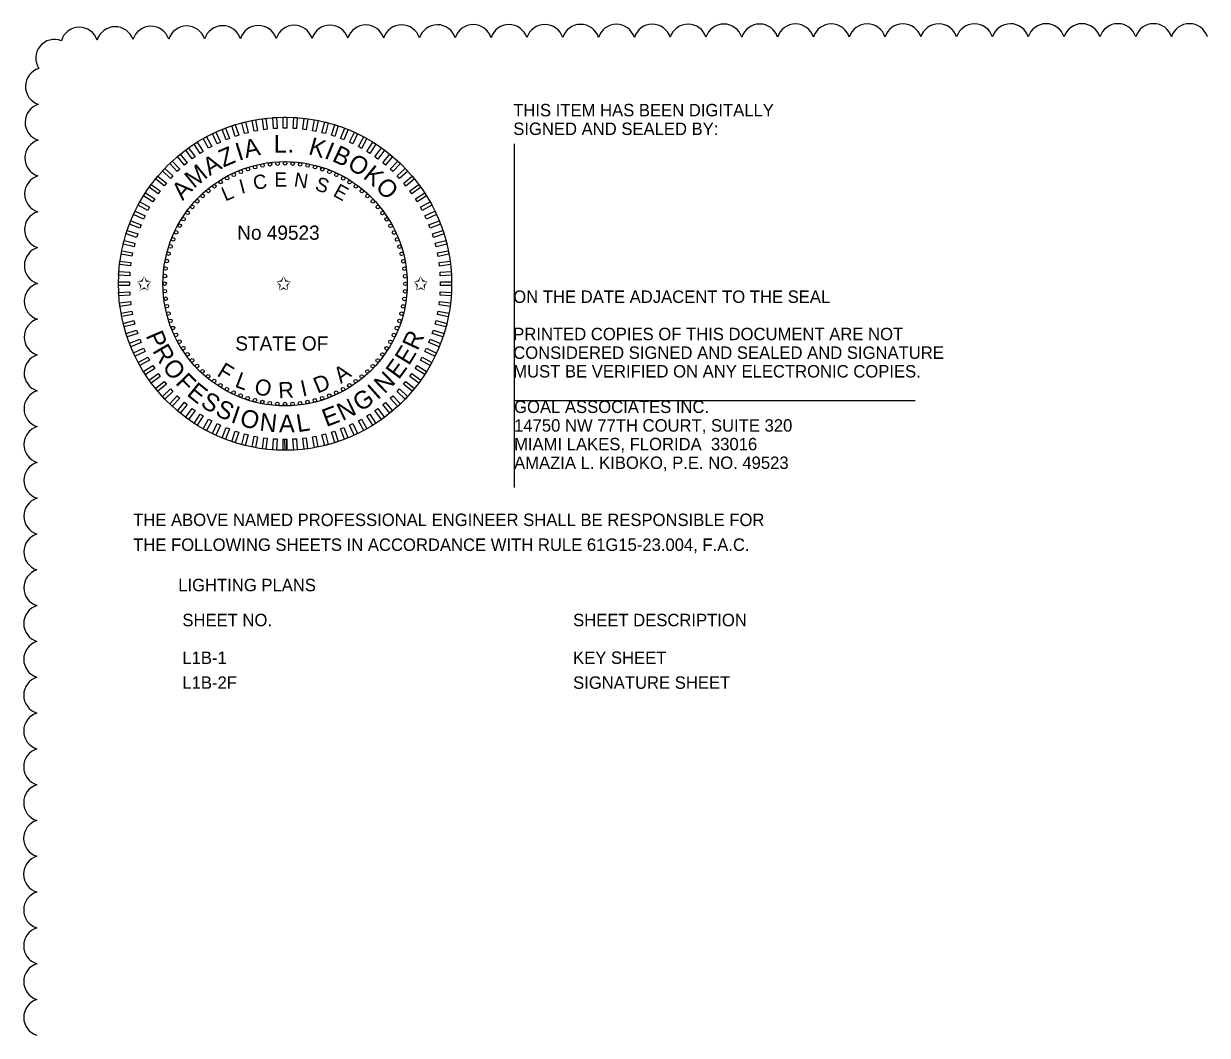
# Model space of a CAD drawing. Extents: x -811.2 to -767.6, y -2295.2 to -2235.1.
# Drawn here: x -783.68 to -777.02, y -2265.59 to -2259.9 of the extents above; entities that cross this region are included whole.
import ezdxf

# ---------------------------------------------------------------- set-up
doc = ezdxf.new("R2010")
doc.units = 0
for name, color, linetype in [('AdhocPoint_dp', 7, 'Continuous'), ('Cloud_dp', 7, 'Continuous'), ('PlotBorder_dp', 7, 'Continuous'), ('TextMinor', 7, 'Continuous'), ('TextMisc', 7, 'Continuous'), ('TextShtNo', 7, 'Continuous')]:
    doc.layers.add(name, color=color, linetype=linetype)

msp = doc.modelspace()

# ---------------------------------------------------------------- linework, layer by layer
at = {"layer": 'AdhocPoint_dp'}
for p, q in [((-780.9186, -2260.5734), (-780.9186, -2262.5081)), ((-780.9186, -2262.0181), (-778.6618, -2262.0181))]:
    msp.add_line(p, q, dxfattribs=at)
at = {"layer": 'Cloud_dp'}
for centre, start, end in [((-782.5594, -2260.0139), 17.87787, 162.87787), ((-782.3579, -2260.0127), 17.82689, 162.82689), ((-782.1564, -2260.0116), 17.78716, 162.78716), ((-781.9548, -2260.0107), 17.75505, 162.75505), ((-781.7533, -2260.0098), 17.72841, 162.72841), ((-781.5518, -2260.009), 17.70584, 162.70584), ((-781.3502, -2260.0084), 17.6864, 162.6864), ((-781.1487, -2260.0077), 17.66942, 162.66942), ((-780.9472, -2260.0072), 17.65443, 162.65443), ((-780.7456, -2260.0066), 17.64106, 162.64106), ((-780.5441, -2260.0062), 17.62905, 162.62905), ((-780.3425, -2260.0057), 17.61817, 162.61817), ((-780.141, -2260.0053), 17.60826, 162.60826), ((-779.9394, -2260.005), 17.59919, 162.59919), ((-779.7379, -2260.0046), 17.59084, 162.59084), ((-779.5364, -2260.0043), 17.58312, 162.58312), ((-779.3348, -2260.004), 17.57595, 162.57595), ((-779.1333, -2260.0038), 17.56928, 162.56928), ((-778.9317, -2260.0036), 17.56305, 162.56305), ((-778.7302, -2260.0033), 17.55721, 162.55721), ((-778.5286, -2260.0032), 17.55172, 162.55172), ((-778.3271, -2260.003), 17.54655, 162.54655), ((-778.1255, -2260.0028), 17.54167, 162.54167), ((-777.924, -2260.0027), 17.53705, 162.53705), ((-777.7224, -2260.0026), 17.53267, 162.53267), ((-777.5209, -2260.0025), 17.52851, 162.52851), ((-777.3194, -2260.0024), 17.52455, 162.52455), ((-777.1178, -2260.0023), 17.52079, 162.52079), ((-783.3652, -2260.0225), 18.59454, 163.59454), ((-783.1638, -2260.0193), 18.21421, 163.21421), ((-782.9624, -2260.0171), 18.04696, 163.04696), ((-782.7609, -2260.0154), 17.94666, 162.94666), ((-783.5053, -2260.0909), 68.43954, 213.43954), ((-783.563, -2260.2503), 106.80445, 251.80445), ((-783.565, -2260.4517), 107.04367, 252.04367), ((-783.5664, -2260.6532), 107.15618, 252.15618), ((-783.5675, -2260.8547), 107.22533, 252.22533), ((-783.5684, -2261.0562), 107.27338, 252.27338), ((-783.5691, -2261.2578), 107.30928, 252.30928), ((-783.5697, -2261.4593), 107.33743, 252.33743), ((-783.5703, -2261.6608), 107.36027, 252.36027), ((-783.5707, -2261.8624), 107.37928, 252.37928), ((-783.5711, -2262.0639), 107.39543, 252.39543), ((-783.5715, -2262.2655), 107.40937, 252.40937), ((-783.5717, -2262.467), 107.42156, 252.42156), ((-783.572, -2262.6685), 107.43234, 252.43234), ((-783.5722, -2262.8701), 107.44197, 252.44197), ((-783.5724, -2263.0716), 107.45063, 252.45063), ((-783.5726, -2263.2732), 107.45847, 252.45847), ((-783.5727, -2263.4747), 107.46563, 252.46563), ((-783.5728, -2263.6763), 107.47218, 252.47218), ((-783.5729, -2263.8778), 107.47822, 252.47822), ((-783.573, -2264.0794), 107.4838, 252.4838), ((-783.573, -2264.2809), 107.48899, 252.48899), ((-783.5731, -2264.4824), 107.49382, 252.49382), ((-783.5731, -2264.684), 107.49843, 252.49843), ((-783.573, -2264.8855), 107.51148, 252.51148), ((-783.573, -2265.0871), 107.53101, 252.53101), ((-783.5728, -2265.2886), 107.55191, 252.55191), ((-783.5726, -2265.4901), 107.57435, 252.57435)]:
    msp.add_arc(centre, 0.1057, start, end, dxfattribs=at)
at = {"layer": 'TextMinor'}
for radius in [0.9375, 0.6875]:
    msp.add_circle((-782.2078, -2261.3603), radius, dxfattribs=at)
at = {"layer": 'TextShtNo'}
for p, q in [((-782.2178, -2262.2978), (-782.218, -2262.2353)), ((-782.2078, -2262.2978), (-782.208, -2262.2353)), ((-782.1978, -2262.2978), (-782.198, -2262.2353))]:
    msp.add_line(p, q, dxfattribs=at)
for points in [[(-782.3618, -2260.4989), (-782.3816, -2260.5026), (-782.3933, -2260.4413), (-782.3735, -2260.4375)], [(-782.3074, -2260.4909), (-782.3274, -2260.4934), (-782.3352, -2260.4315), (-782.3152, -2260.4289)], [(-782.2526, -2260.4864), (-782.2727, -2260.4876), (-782.2767, -2260.4253), (-782.2565, -2260.424)], [(-782.1976, -2260.4853), (-782.2178, -2260.4853), (-782.2178, -2260.4228), (-782.1976, -2260.4228)], [(-782.1427, -2260.4876), (-782.1629, -2260.4864), (-782.1589, -2260.4241), (-782.1388, -2260.4253)], [(-782.088, -2260.4934), (-782.1081, -2260.4909), (-782.1002, -2260.429), (-782.0802, -2260.4315)], [(-782.0338, -2260.5027), (-782.0537, -2260.4989), (-782.042, -2260.4376), (-782.0221, -2260.4413)], [(-782.5712, -2260.5642), (-782.5894, -2260.5728), (-782.616, -2260.5163), (-782.5978, -2260.5077)], [(-782.5205, -2260.543), (-782.5392, -2260.5504), (-782.5622, -2260.4923), (-782.5434, -2260.4849)], [(-782.4685, -2260.525), (-782.4877, -2260.5312), (-782.507, -2260.4718), (-782.4878, -2260.4656)], [(-782.4156, -2260.5102), (-782.4351, -2260.5152), (-782.4506, -2260.4548), (-782.4311, -2260.4498)], [(-781.9803, -2260.5153), (-781.9999, -2260.5103), (-781.9844, -2260.4498), (-781.9648, -2260.4548)], [(-781.9277, -2260.5312), (-781.9469, -2260.525), (-781.9276, -2260.4656), (-781.9084, -2260.4719)], [(-781.8762, -2260.5505), (-781.895, -2260.543), (-781.872, -2260.485), (-781.8532, -2260.4924)], [(-781.826, -2260.5729), (-781.8443, -2260.5643), (-781.8177, -2260.5078), (-781.7994, -2260.5164)], [(-782.6681, -2260.616), (-782.6851, -2260.6268), (-782.7186, -2260.5741), (-782.7015, -2260.5633)], [(-782.6204, -2260.5886), (-782.6381, -2260.5983), (-782.6682, -2260.5436), (-782.6505, -2260.5339)], [(-781.7773, -2260.5984), (-781.795, -2260.5887), (-781.7649, -2260.534), (-781.7473, -2260.5437)], [(-781.7303, -2260.6269), (-781.7474, -2260.6161), (-781.7139, -2260.5634), (-781.6969, -2260.5742)], [(-782.7577, -2260.6796), (-782.7733, -2260.6925), (-782.8131, -2260.6443), (-782.7975, -2260.6315)], [(-782.7139, -2260.6464), (-782.7302, -2260.6583), (-782.7669, -2260.6078), (-782.7506, -2260.5959)], [(-781.6852, -2260.6584), (-781.7016, -2260.6465), (-781.6649, -2260.596), (-781.6485, -2260.6079)], [(-781.6422, -2260.6926), (-781.6578, -2260.6797), (-781.618, -2260.6316), (-781.6024, -2260.6445)], [(-782.7994, -2260.7155), (-782.8141, -2260.7293), (-782.8568, -2260.6838), (-782.8421, -2260.6699)], [(-781.6014, -2260.7294), (-781.6161, -2260.7156), (-781.5734, -2260.6701), (-781.5586, -2260.6839)], [(-782.8755, -2260.7947), (-782.8884, -2260.8102), (-782.9365, -2260.7704), (-782.9237, -2260.7549)], [(-782.8387, -2260.7539), (-782.8525, -2260.7686), (-782.898, -2260.7258), (-782.8842, -2260.7111)], [(-781.563, -2260.7687), (-781.5768, -2260.754), (-781.5313, -2260.7113), (-781.5175, -2260.726)], [(-781.5271, -2260.8104), (-781.54, -2260.7948), (-781.4919, -2260.755), (-781.479, -2260.7706)], [(-782.9097, -2260.8377), (-782.9216, -2260.8541), (-782.9721, -2260.8174), (-782.9603, -2260.801)], [(-781.4939, -2260.8542), (-781.5058, -2260.8379), (-781.4553, -2260.8012), (-781.4434, -2260.8175)], [(-782.9697, -2260.9298), (-782.9794, -2260.9475), (-783.0341, -2260.9174), (-783.0244, -2260.8997)], [(-782.9412, -2260.8828), (-782.952, -2260.8999), (-783.0047, -2260.8664), (-782.9939, -2260.8494)], [(-781.4635, -2260.9), (-781.4744, -2260.883), (-781.4216, -2260.8495), (-781.4108, -2260.8666)], [(-781.4361, -2260.9477), (-781.4458, -2260.93), (-781.3911, -2260.8999), (-781.3814, -2260.9176)], [(-782.9952, -2260.9785), (-783.0038, -2260.9968), (-783.0603, -2260.9702), (-783.0517, -2260.9519)], [(-781.4117, -2260.9969), (-781.4203, -2260.9787), (-781.3638, -2260.9521), (-781.3552, -2260.9704)], [(-783.0176, -2261.0287), (-783.0251, -2261.0475), (-783.0831, -2261.0245), (-783.0757, -2261.0057)], [(-781.3905, -2261.0477), (-781.3979, -2261.0289), (-781.3399, -2261.0059), (-781.3324, -2261.0247)], [(-783.0369, -2261.0802), (-783.0431, -2261.0994), (-783.1025, -2261.0801), (-783.0963, -2261.0609)], [(-781.3725, -2261.0996), (-781.3787, -2261.0804), (-781.3193, -2261.0611), (-781.3131, -2261.0803)], [(-783.0654, -2261.1863), (-783.0692, -2261.2062), (-783.1306, -2261.1945), (-783.1268, -2261.1746)], [(-783.0528, -2261.1328), (-783.0578, -2261.1524), (-783.1183, -2261.1368), (-783.1133, -2261.1173)], [(-781.3577, -2261.1526), (-781.3628, -2261.133), (-781.3023, -2261.1175), (-781.2973, -2261.137)], [(-781.3464, -2261.2063), (-781.3502, -2261.1865), (-781.2888, -2261.1748), (-781.285, -2261.1946)], [(-783.0747, -2261.2405), (-783.0772, -2261.2606), (-783.1391, -2261.2527), (-783.1366, -2261.2327)], [(-781.3384, -2261.2607), (-781.3409, -2261.2407), (-781.279, -2261.2329), (-781.2765, -2261.2529)], [(-783.0805, -2261.2952), (-783.0817, -2261.3153), (-783.1441, -2261.3114), (-783.1428, -2261.2913)], [(-781.3339, -2261.3155), (-781.3351, -2261.2954), (-781.2728, -2261.2915), (-781.2716, -2261.3116)], [(-783.0828, -2261.3501), (-783.0828, -2261.3703), (-783.1453, -2261.3703), (-783.1453, -2261.3501)], [(-781.3328, -2261.3705), (-781.3328, -2261.3503), (-781.2703, -2261.3503), (-781.2703, -2261.3705)], [(-783.0818, -2261.4051), (-783.0805, -2261.4252), (-783.1428, -2261.4291), (-783.1441, -2261.409)], [(-781.3351, -2261.4254), (-781.3339, -2261.4053), (-781.2716, -2261.4092), (-781.2728, -2261.4293)], [(-783.0772, -2261.4599), (-783.0747, -2261.4799), (-783.1366, -2261.4877), (-783.1392, -2261.4677)], [(-781.341, -2261.4801), (-781.3384, -2261.4601), (-781.2765, -2261.4679), (-781.279, -2261.4879)], [(-783.0693, -2261.5143), (-783.0655, -2261.5341), (-783.1268, -2261.5458), (-783.1306, -2261.526)], [(-783.0579, -2261.568), (-783.0529, -2261.5876), (-783.1133, -2261.6031), (-783.1184, -2261.5836)], [(-781.3628, -2261.5878), (-781.3578, -2261.5682), (-781.2973, -2261.5838), (-781.3023, -2261.6033)], [(-781.3502, -2261.5343), (-781.3464, -2261.5144), (-781.2851, -2261.5261), (-781.2889, -2261.546)], [(-783.0432, -2261.621), (-783.0369, -2261.6402), (-783.0963, -2261.6595), (-783.1025, -2261.6403)], [(-781.3788, -2261.6404), (-781.3725, -2261.6212), (-781.3131, -2261.6405), (-781.3194, -2261.6597)], [(-783.0251, -2261.673), (-783.0177, -2261.6917), (-783.0758, -2261.7147), (-783.0832, -2261.6959)], [(-781.398, -2261.6919), (-781.3906, -2261.6731), (-781.3325, -2261.6961), (-781.3399, -2261.7149)], [(-783.0039, -2261.7237), (-782.9953, -2261.7419), (-783.0518, -2261.7685), (-783.0604, -2261.7502)], [(-782.9795, -2261.7729), (-782.9698, -2261.7906), (-783.0245, -2261.8207), (-783.0342, -2261.803)], [(-781.4459, -2261.7908), (-781.4362, -2261.7731), (-781.3815, -2261.8032), (-781.3912, -2261.8209)], [(-781.4204, -2261.7421), (-781.4118, -2261.7238), (-781.3553, -2261.7504), (-781.3639, -2261.7687)], [(-782.9521, -2261.8206), (-782.9413, -2261.8376), (-782.994, -2261.8711), (-783.0048, -2261.854)], [(-781.4745, -2261.8378), (-781.4636, -2261.8207), (-781.4109, -2261.8542), (-781.4217, -2261.8712)], [(-782.9217, -2261.8664), (-782.9099, -2261.8827), (-782.9604, -2261.9194), (-782.9722, -2261.9031)], [(-781.5059, -2261.8829), (-781.494, -2261.8665), (-781.4435, -2261.9032), (-781.4554, -2261.9196)], [(-782.8885, -2261.9102), (-782.8757, -2261.9258), (-782.9238, -2261.9656), (-782.9366, -2261.95)], [(-782.8527, -2261.9519), (-782.8388, -2261.9666), (-782.8844, -2262.0093), (-782.8982, -2261.9946)], [(-781.5769, -2261.9667), (-781.5631, -2261.952), (-781.5176, -2261.9948), (-781.5314, -2262.0095)], [(-781.5401, -2261.9259), (-781.5272, -2261.9104), (-781.4791, -2261.9502), (-781.492, -2261.9657)], [(-782.8142, -2261.9912), (-782.7995, -2262.005), (-782.8423, -2262.0505), (-782.857, -2262.0367)], [(-782.7734, -2262.028), (-782.7579, -2262.0409), (-782.7977, -2262.089), (-782.8132, -2262.0761)], [(-781.6579, -2262.041), (-781.6423, -2262.0281), (-781.6025, -2262.0763), (-781.6181, -2262.0891)], [(-781.6162, -2262.0051), (-781.6015, -2261.9913), (-781.5588, -2262.0368), (-781.5735, -2262.0507)], [(-782.7304, -2262.0622), (-782.7141, -2262.0741), (-782.7508, -2262.1246), (-782.7671, -2262.1127)], [(-782.6853, -2262.0937), (-782.6682, -2262.1045), (-782.7017, -2262.1572), (-782.7187, -2262.1464)], [(-781.7475, -2262.1046), (-781.7305, -2262.0938), (-781.697, -2262.1465), (-781.7141, -2262.1573)], [(-781.7017, -2262.0742), (-781.6854, -2262.0623), (-781.6487, -2262.1129), (-781.665, -2262.1247)], [(-782.6383, -2262.1222), (-782.6206, -2262.1319), (-782.6507, -2262.1866), (-782.6684, -2262.1769)], [(-782.5896, -2262.1477), (-782.5713, -2262.1563), (-782.5979, -2262.2128), (-782.6162, -2262.2042)], [(-782.5394, -2262.1701), (-782.5206, -2262.1776), (-782.5436, -2262.2356), (-782.5624, -2262.2282)], [(-781.8952, -2262.1776), (-781.8764, -2262.1702), (-781.8534, -2262.2283), (-781.8722, -2262.2357)], [(-781.8445, -2262.1564), (-781.8262, -2262.1478), (-781.7996, -2262.2043), (-781.8179, -2262.2129)], [(-781.7952, -2262.132), (-781.7775, -2262.1223), (-781.7474, -2262.177), (-781.7651, -2262.1867)], [(-782.4879, -2262.1894), (-782.4687, -2262.1956), (-782.488, -2262.255), (-782.5072, -2262.2487)], [(-782.4353, -2262.2053), (-782.4157, -2262.2103), (-782.4313, -2262.2708), (-782.4508, -2262.2658)], [(-782.3818, -2262.2179), (-782.362, -2262.2217), (-782.3737, -2262.283), (-782.3935, -2262.2793)], [(-782.3276, -2262.2272), (-782.3076, -2262.2297), (-782.3154, -2262.2916), (-782.3354, -2262.2891)], [(-782.2729, -2262.233), (-782.2528, -2262.2342), (-782.2567, -2262.2966), (-782.2768, -2262.2953)], [(-782.218, -2262.2353), (-782.1978, -2262.2353), (-782.1978, -2262.2978), (-782.218, -2262.2978)], [(-782.163, -2262.2342), (-782.1429, -2262.233), (-782.139, -2262.2953), (-782.1591, -2262.2966)], [(-782.1082, -2262.2297), (-782.0882, -2262.2272), (-782.0804, -2262.2891), (-782.1004, -2262.2917)], [(-782.0539, -2262.2217), (-782.034, -2262.218), (-782.0223, -2262.2793), (-782.0422, -2262.2831)], [(-782.0001, -2262.2104), (-781.9805, -2262.2054), (-781.965, -2262.2658), (-781.9845, -2262.2709)], [(-781.9471, -2262.1957), (-781.9279, -2262.1894), (-781.9086, -2262.2488), (-781.9278, -2262.255)]]:
    msp.add_lwpolyline(points, close=True, dxfattribs=at)
for centre in [(-782.4166, -2260.7158), (-782.3757, -2260.704), (-782.3342, -2260.6947), (-782.2922, -2260.6881), (-782.2498, -2260.6841), (-782.2072, -2260.6828), (-782.1647, -2260.6842), (-782.1223, -2260.6882), (-782.0803, -2260.6949), (-782.0388, -2260.7043), (-781.9979, -2260.7162), (-782.5337, -2260.7664), (-782.4958, -2260.7471), (-782.4567, -2260.7302), (-781.9579, -2260.7306), (-781.9189, -2260.7476), (-781.8809, -2260.7669), (-782.6392, -2260.8379), (-782.6056, -2260.8119), (-782.5703, -2260.788), (-781.8443, -2260.7886), (-781.8092, -2260.8125), (-781.7755, -2260.8387), (-782.7013, -2260.8961), (-782.6712, -2260.8661), (-781.7436, -2260.8668), (-781.7136, -2260.897), (-782.7556, -2260.9616), (-782.7295, -2260.928), (-781.6855, -2260.9289), (-781.6594, -2260.9626), (-782.8012, -2261.0334), (-782.7795, -2260.9968), (-781.6355, -2260.9978), (-781.6139, -2261.0344), (-782.8375, -2261.1104), (-782.8206, -2261.0713), (-781.5946, -2261.0724), (-781.5777, -2261.1114), (-782.852, -2261.1504), (-781.5633, -2261.1515), (-782.8732, -2261.2328), (-782.8639, -2261.1913), (-781.5515, -2261.1924), (-781.5422, -2261.2339), (-782.8839, -2261.3172), (-782.8799, -2261.2748), (-781.5356, -2261.276), (-782.8853, -2261.3597), (-781.5316, -2261.3183), (-781.5303, -2261.3609), (-782.884, -2261.4023), (-782.88, -2261.4447), (-781.5358, -2261.4458), (-781.5317, -2261.4034), (-782.8734, -2261.4867), (-781.5425, -2261.4878), (-782.8641, -2261.5282), (-782.8523, -2261.5691), (-781.5637, -2261.5702), (-781.5518, -2261.5293), (-782.8379, -2261.6092), (-782.821, -2261.6482), (-781.5951, -2261.6493), (-781.5781, -2261.6102), (-782.8018, -2261.6862), (-781.6144, -2261.6872), (-782.7801, -2261.7228), (-782.7562, -2261.7581), (-781.6601, -2261.759), (-781.6361, -2261.7238), (-782.7302, -2261.7917), (-782.7021, -2261.8236), (-781.7143, -2261.8245), (-781.6862, -2261.7926), (-782.672, -2261.8538), (-782.6401, -2261.8819), (-782.6065, -2261.9081), (-781.8101, -2261.9087), (-781.7764, -2261.8827), (-781.7445, -2261.8545), (-782.5713, -2261.932), (-782.5347, -2261.9537), (-782.4968, -2261.9731), (-781.9199, -2261.9735), (-781.8819, -2261.9542), (-781.8453, -2261.9326), (-782.4577, -2261.99), (-782.4177, -2262.0044), (-782.3768, -2262.0163), (-782.3353, -2262.0257), (-782.2933, -2262.0324), (-782.2509, -2262.0364), (-782.2078, -2262.0378), (-782.1658, -2262.0365), (-782.1235, -2262.0325), (-782.0814, -2262.0259), (-782.0399, -2262.0166), (-781.999, -2262.0048), (-781.9589, -2261.9904)]:
    msp.add_circle(centre, 0.01, dxfattribs=at)

# ---------------------------------------------------------------- texts
at = {"layer": 'PlotBorder_dp'}
for s, height, p in [('THIS ITEM HAS BEEN DIGITALLY', 0.07, (-780.9235, -2260.4183)), ('SIGNED AND SEALED BY:', 0.07, (-780.9235, -2260.5233)), ('No 49523', 0.08, (-782.4768, -2261.1131)), ('ON THE DATE ADJACENT TO THE SEAL', 0.07, (-780.9235, -2261.4683)), ('PRINTED COPIES OF THIS DOCUMENT ARE NOT ', 0.07, (-780.9235, -2261.6783)), ('STATE OF', 0.08, (-782.4875, -2261.7365)), ('CONSIDERED SIGNED AND SEALED AND SIGNATURE ', 0.07, (-780.9235, -2261.7833)), ('MUST BE VERIFIED ON ANY ELECTRONIC COPIES.', 0.07, (-780.9235, -2261.8883)), ('GOAL ASSOCIATES INC.', 0.07, (-780.9186, -2262.0881)), ('14750 NW 77TH COURT, SUITE 320', 0.07, (-780.9186, -2262.1931)), ('MIAMI LAKES, FLORIDA  33016', 0.07, (-780.9186, -2262.2981)), ('AMAZIA L. KIBOKO, P.E. NO. 49523', 0.07, (-780.9186, -2262.4031)), ('THE ABOVE NAMED PROFESSIONAL ENGINEER SHALL BE RESPONSIBLE FOR ', 0.07, (-783.0626, -2262.7243)), ('THE FOLLOWING SHEETS IN ACCORDANCE WITH RULE 61G15-23.004, F.A.C.', 0.07, (-783.0626, -2262.8643)), ('LIGHTING PLANS', 0.07, (-782.8089, -2263.0913))]:
    msp.add_text(s, height=height, dxfattribs=at).set_placement(p)
for s, height, rotation, p in [('I', 0.1, 17.68363, (-782.4679, -2260.6694)), ('A', 0.1, 11.91844, (-782.4286, -2260.6534)), ('L', 0.1, 359.96623, (-782.2714, -2260.623)), ('K', 0.1, 344.27273, (-782.0807, -2260.6302)), ('I', 0.1, 337.77772, (-781.9921, -2260.652)), ('Z', 0.1, 23.30524, (-782.5548, -2260.707)), ('.', 0.1, 353.78581, (-782.1947, -2260.6201)), ('B', 0.1, 334.48695, (-781.9482, -2260.6673)), ('O', 0.1, 327.82385, (-781.8635, -2260.7059)), ('M', 0.1, 39.30005, (-782.7212, -2260.8277)), ('A', 0.1, 31.46601, (-782.6322, -2260.7556)), ('K', 0.1, 321.0594, (-781.7739, -2260.7631)), ('O', 0.1, 314.20329, (-781.7043, -2260.8207)), ('A', 0.1, 46.80938, (-782.7835, -2260.8962)), ('P', 0.1, 293.19548, (-782.9935, -2261.6519)), ('R', 0.1, 65.28865, (-781.4614, -2261.7412)), ('R', 0.1, 300.25949, (-782.9566, -2261.7378)), ('E', 0.1, 58.61694, (-781.5106, -2261.8252)), ('O', 0.1, 307.26617, (-782.9025, -2261.8296)), ('F', 0.09, 328.53399, (-782.5962, -2261.8756)), ('A', 0.09, 35.54629, (-781.8934, -2261.9249)), ('E', 0.1, 53.99864, (-781.5679, -2261.9039)), ('F', 0.1, 314.20329, (-782.8291, -2261.9221)), ('L', 0.09, 339.48752, (-782.495, -2261.9386)), ('O', 0.09, 348.08156, (-782.3856, -2261.9792)), ('I', 0.09, 12.52485, (-782.1092, -2261.9963)), ('D', 0.09, 22.22228, (-782.0251, -2261.9794)), ('N', 0.1, 44.34211, (-781.6479, -2261.9838)), ('E', 0.1, 321.0594, (-782.7657, -2261.9857)), ('R', 0.09, 3.10738, (-782.2434, -2262.0054)), ('G', 0.1, 34.11362, (-781.7834, -2262.084)), ('I', 0.1, 41.83906, (-781.6873, -2262.018)), ('S', 0.1, 327.82385, (-782.6895, -2262.0462)), ('S', 0.1, 334.48695, (-782.6064, -2262.0976)), ('N', 0.1, 26.0618, (-781.8846, -2262.1342)), ('I', 0.1, 341.03996, (-782.5178, -2262.1389)), ('O', 0.1, 344.27273, (-782.4687, -2262.1565)), ('N', 0.1, 353.78581, (-782.3543, -2262.1864)), ('A', 0.1, 359.96623, (-782.242, -2262.1974)), ('L', 0.1, 8.98261, (-782.1363, -2262.1966)), ('E', 0.1, 20.51248, (-781.9761, -2262.1675))]:
    msp.add_text(s, height=height, rotation=rotation, dxfattribs=at).set_placement(p)
at = {"layer": 'TextMisc'}
for s, p in [('SHEET NO.', (-782.7855, -2263.2883)), ('SHEET DESCRIPTION', (-780.5865, -2263.2883)), ('L1B-1', (-782.7855, -2263.5005)), ('KEY SHEET', (-780.5865, -2263.5005)), ('L1B-2F', (-782.7855, -2263.6405)), ('SIGNATURE SHEET', (-780.5865, -2263.6405))]:
    msp.add_text(s, height=0.07, dxfattribs=at).set_placement(p)
at = {"layer": 'TextShtNo'}
for s, rotation, p in [('I', 14.81888, (-782.4534, -2260.8551)), ('C', 8.98261, (-782.3808, -2260.8324)), ('E', 359.96623, (-782.2681, -2260.8135)), ('N', 350.64643, (-782.1612, -2260.8121)), ('S', 341.03996, (-782.0441, -2260.8309)), ('L', 23.30524, (-782.544, -2260.898)), ('E', 331.16864, (-781.9426, -2260.8635))]:
    msp.add_text(s, height=0.08, rotation=rotation, dxfattribs=at).set_placement(p)
for p in [(-783.0428, -2261.3983), (-782.2581, -2261.3983), (-781.4862, -2261.3983)]:
    msp.add_text('✩', height=0.08, dxfattribs=at).set_placement(p)

doc.saveas('drawing.dxf')
